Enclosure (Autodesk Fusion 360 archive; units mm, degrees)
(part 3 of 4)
sketch "Sketch47" plane through (0, 0, 11.21) normal (0, 0, 1) x axis (-1, 0, 0)
  line L1 (-247.2132, -356.5) -> (-247.2132, -307.5)
  line L2 (-303.7132, -364) -> (-254.7132, -364)
  line L3 (-311.2132, -307.5) -> (-311.2132, -356.5)
  line L4 (-254.7132, -300) -> (-303.7132, -300)
  line L5 (-147.4232, -321.735) -> (-217.4232, -321.735)
  line L6 (-217.4232, -336.735) -> (-147.4232, -336.735)
  line L7 (-110.1332, -364) -> (-61.1332, -364)
  line L8 (-117.6332, -307.5) -> (-117.6332, -356.5)
  line L9 (-61.1332, -300) -> (-110.1332, -300)
  line L10 (-53.6332, -356.5) -> (-53.6332, -307.5)
  line L11 (-33.6332, -368.47) -> (-331.2132, -368.47)
  line L12 (-33.6332, -290) -> (-33.6332, -368.47)
  line L13 (-331.2132, -290) -> (-33.6332, -290)
  line L14 (-331.2132, -368.47) -> (-331.2132, -290)
  line L15 (-333.79, -258.79) -> (-36.21, -258.79)
  line L16 (-348.79, -36.21) -> (-348.79, -243.79)
  line L17 (-36.21, -21.21) -> (-333.79, -21.21)
  line L18 (-21.21, -243.79) -> (-21.21, -36.21)
  line L19 (-25, -270) -> (-345, -270)
  line L20 (-10, -25) -> (-10, -255)
  line L21 (-345, -10) -> (-25, -10)
  line L22 (-360, -255) -> (-360, -25)
  line L23 (-175, -248.79) -> (-46.21, -248.79)
  line L24 (-325.1297, -248.79) -> (-195, -248.79)
  line L25 (-338.79, -44.8703) -> (-338.79, -235.1297)
  line L26 (-195, -31.21) -> (-325.1297, -31.21)
  line L27 (-44.8703, -31.21) -> (-175, -31.21)
  line L28 (-31.21, -233.79) -> (-31.21, -44.8703)
  line L29 (-36.21, -258.79) -> (-333.79, -258.79)
  line L30 (-21.21, -36.21) -> (-21.21, -243.79)
  line L31 (-333.79, -21.21) -> (-36.21, -21.21)
  line L32 (-348.79, -243.79) -> (-348.79, -36.21)
  line L33 (-58.6332, -356.5) -> (-58.6332, -307.5)
  line L34 (-110.1332, -359) -> (-61.1332, -359)
  line L35 (-112.6332, -307.5) -> (-112.6332, -356.5)
  line L36 (-61.1332, -305) -> (-110.1332, -305)
  line L37 (-117.6332, -356.5) -> (-117.6332, -307.5)
  line L38 (-61.1332, -364) -> (-110.1332, -364)
  line L39 (-53.6332, -307.5) -> (-53.6332, -356.5)
  line L40 (-110.1332, -300) -> (-61.1332, -300)
  line L41 (-254.7132, -305) -> (-303.7132, -305)
  line L42 (-252.2132, -356.5) -> (-252.2132, -307.5)
  line L43 (-303.7132, -359) -> (-254.7132, -359)
  line L44 (-306.2132, -307.5) -> (-306.2132, -356.5)
  line L45 (-254.7132, -305) -> (-303.7132, -305)
  line L46 (-254.7132, -364) -> (-303.7132, -364)
  line L47 (-247.2132, -307.5) -> (-247.2132, -356.5)
  line L48 (-303.7132, -300) -> (-254.7132, -300)
  line L49 (-311.2132, -356.5) -> (-311.2132, -307.5)
  arc A1 centre (-254.7132, -356.5) radius 7.5 clockwise from (-247.2132, -356.5) to (-254.7132, -364)
  arc A2 centre (-303.7132, -356.5) radius 7.5 clockwise from (-303.7132, -364) to (-311.2132, -356.5)
  arc A3 centre (-303.7132, -307.5) radius 7.5 clockwise from (-311.2132, -307.5) to (-303.7132, -300)
  arc A4 centre (-254.7132, -307.5) radius 7.5 clockwise from (-254.7132, -300) to (-247.2132, -307.5)
  arc A5 centre (-217.4232, -329.235) radius 7.5 clockwise from (-217.4232, -336.735) to (-217.4232, -321.735)
  arc A6 centre (-147.4232, -329.235) radius 7.5 clockwise from (-147.4232, -321.735) to (-147.4232, -336.735)
  arc A7 centre (-110.1332, -356.5) radius 7.5 clockwise from (-110.1332, -364) to (-117.6332, -356.5)
  arc A8 centre (-110.1332, -307.5) radius 7.5 clockwise from (-117.6332, -307.5) to (-110.1332, -300)
  arc A9 centre (-61.1332, -307.5) radius 7.5 clockwise from (-61.1332, -300) to (-53.6332, -307.5)
  arc A10 centre (-61.1332, -356.5) radius 7.5 clockwise from (-53.6332, -356.5) to (-61.1332, -364)
  arc A11 centre (-333.79, -243.79) radius 15 clockwise from (-333.79, -258.79) to (-348.79, -243.79)
  arc A12 centre (-333.79, -36.21) radius 15 clockwise from (-348.79, -36.21) to (-333.79, -21.21)
  arc A13 centre (-36.21, -36.21) radius 15 clockwise from (-36.21, -21.21) to (-21.21, -36.21)
  arc A14 centre (-36.21, -243.79) radius 15 clockwise from (-21.21, -243.79) to (-36.21, -258.79)
  arc A15 centre (-25, -255) radius 15 clockwise from (-10, -255) to (-25, -270)
  arc A16 centre (-25, -25) radius 15 clockwise from (-25, -10) to (-10, -25)
  arc A17 centre (-345, -25) radius 15 clockwise from (-360, -25) to (-345, -10)
  arc A18 centre (-345, -255) radius 15 clockwise from (-345, -270) to (-360, -255)
  arc A19 centre (-46.21, -233.79) radius 15 clockwise from (-44.9029, -248.7329) to (-46.21, -248.79)
  arc A20 centre (-185, -248.79) radius 10 clockwise from (-195, -248.79) to (-175, -248.79)
  arc A21 centre (-333.79, -243.79) radius 10 clockwise from (-338.79, -235.1297) to (-325.1297, -248.79)
  arc A22 centre (-333.79, -36.21) radius 10 clockwise from (-325.1297, -31.21) to (-338.79, -44.8703)
  arc A23 centre (-185, -31.21) radius 10 clockwise from (-175, -31.21) to (-195, -31.21)
  arc A24 centre (-36.21, -36.21) radius 10 clockwise from (-31.21, -44.8703) to (-44.8703, -31.21)
  arc A25 centre (-46.21, -233.79) radius 15 clockwise from (-31.21, -233.79) to (-31.2671, -235.0971)
  arc A26 centre (-36.21, -243.79) radius 10 clockwise from (-44.9029, -248.7329) to (-31.2671, -235.0971)
  arc A27 centre (-36.21, -243.79) radius 15 clockwise from (-21.21, -243.79) to (-36.21, -258.79)
  arc A28 centre (-36.21, -36.21) radius 15 clockwise from (-36.21, -21.21) to (-21.21, -36.21)
  arc A29 centre (-333.79, -36.21) radius 15 clockwise from (-348.79, -36.21) to (-333.79, -21.21)
  arc A30 centre (-333.79, -243.79) radius 15 clockwise from (-333.79, -258.79) to (-348.79, -243.79)
  arc A31 centre (-61.1332, -307.5) radius 2.5 clockwise from (-61.1332, -305) to (-58.6332, -307.5)
  arc A32 centre (-61.1332, -356.5) radius 2.5 clockwise from (-58.6332, -356.5) to (-61.1332, -359)
  arc A33 centre (-110.1332, -356.5) radius 2.5 clockwise from (-110.1332, -359) to (-112.6332, -356.5)
  arc A34 centre (-110.1332, -307.5) radius 2.5 clockwise from (-112.6332, -307.5) to (-110.1332, -305)
  arc A35 centre (-110.1332, -307.5) radius 7.5 clockwise from (-117.6332, -307.5) to (-110.1332, -300)
  arc A36 centre (-110.1332, -356.5) radius 7.5 clockwise from (-110.1332, -364) to (-117.6332, -356.5)
  arc A37 centre (-61.1332, -356.5) radius 7.5 clockwise from (-53.6332, -356.5) to (-61.1332, -364)
  arc A38 centre (-61.1332, -307.5) radius 7.5 clockwise from (-61.1332, -300) to (-53.6332, -307.5)
  arc A39 centre (-254.7132, -307.5) radius 2.5 clockwise from (-254.7132, -305) to (-252.2132, -307.5)
  arc A40 centre (-254.7132, -356.5) radius 2.5 clockwise from (-252.2132, -356.5) to (-254.7132, -359)
  arc A41 centre (-303.7132, -356.5) radius 2.5 clockwise from (-303.7132, -359) to (-306.2132, -356.5)
  arc A42 centre (-303.7132, -307.5) radius 2.5 clockwise from (-306.2132, -307.5) to (-303.7132, -305)
  arc A43 centre (-303.7132, -356.5) radius 7.5 clockwise from (-303.7132, -364) to (-311.2132, -356.5)
  arc A44 centre (-254.7132, -356.5) radius 7.5 clockwise from (-247.2132, -356.5) to (-254.7132, -364)
  arc A45 centre (-254.7132, -307.5) radius 7.5 clockwise from (-254.7132, -300) to (-247.2132, -307.5)
  arc A46 centre (-303.7132, -307.5) radius 7.5 clockwise from (-311.2132, -307.5) to (-303.7132, -300)
sketch "Sketch48" plane through (0, -162.2304, 59.047) normal (0, 0.9397, -0.342) x axis (-1, 0, 0)
  line L1 (-46.5, 2.5998) -> (-46.5, -10.4002)
  line L2 (-45, 2.5998) -> (-46.5, 2.5998)
  line L3 (-41.5, 7.5998) -> (-41.5, 6.0998)
  line L4 (41.5, 7.5998) -> (-41.5, 7.5998)
  line L5 (41.5, 6.0998) -> (41.5, 7.5998)
  line L6 (46.5, 2.5998) -> (45, 2.5998)
  line L7 (46.5, -10.4002) -> (46.5, 2.5998)
  line L8 (45, -10.4002) -> (46.5, -10.4002)
  line L9 (41.5, -15.4002) -> (41.5, -13.9002)
  line L10 (-41.5, -15.4002) -> (41.5, -15.4002)
  line L11 (-41.5, -13.9002) -> (-41.5, -15.4002)
  line L12 (-46.5, -10.4002) -> (-45, -10.4002)
  line L13 (-47, -15.9002) -> (-47, 8.0998)
  line L14 (47, -15.9002) -> (-47, -15.9002)
  line L15 (47, 8.0998) -> (47, -15.9002)
  line L16 (-47, 8.0998) -> (47, 8.0998)
  arc A1 centre (-45, 6.0998) radius 3.5 clockwise from (-41.5, 6.0998) to (-45, 2.5998)
  arc A2 centre (45, 6.0998) radius 3.5 clockwise from (45, 2.5998) to (41.5, 6.0998)
  arc A3 centre (45, -13.9002) radius 3.5 clockwise from (41.5, -13.9002) to (45, -10.4002)
  arc A4 centre (-45, -13.9002) radius 3.5 clockwise from (-45, -10.4002) to (-41.5, -13.9002)
  circle C1 centre (45, -13.9002) radius 1.5
  circle C2 centre (-45, 6.0998) radius 1.5
  circle C3 centre (45, 6.0998) radius 1.5
  circle C4 centre (-45, -13.9002) radius 1.5
offset_faces "OffsetFaces4" distance -1
fillet "Fillet7" radius 3.5
split "Split3" bodies "CASE (1)"
offset_faces "OffsetFaces6" distance 6
offset_faces "OffsetFaces7" distance 6
offset_faces "OffsetFaces8" distance -6
offset_faces "OffsetFaces9" distance -6
sketch "Sketch63" plane through (0, -160.351, 58.363) normal (0, -0.9397, 0.342) x axis (1, 0, 0)
  line L1 (50, 12.0998) -> (50, -19.9002)
  line L2 (-45, 17.0998) -> (45, 17.0998)
  line L3 (-50, -19.9002) -> (-50, 12.0998)
  line L4 (45, -24.9002) -> (-45, -24.9002)
  line L5 (-41.5, -13.9002) -> (-41.5, -15.4002)
  line L6 (-46.5, -10.4002) -> (-45, -10.4002)
  line L7 (-46.5, 2.5998) -> (-46.5, -10.4002)
  line L8 (-45, 2.5998) -> (-46.5, 2.5998)
  line L9 (-41.5, 7.5998) -> (-41.5, 6.0998)
  line L10 (41.5, 7.5998) -> (-41.5, 7.5998)
  line L11 (41.5, 6.0998) -> (41.5, 7.5998)
  line L12 (46.5, 2.5998) -> (45, 2.5998)
  line L13 (46.5, -10.4002) -> (46.5, 2.5998)
  line L14 (45, -10.4002) -> (46.5, -10.4002)
  line L15 (41.5, -15.4002) -> (41.5, -13.9002)
  line L16 (-41.5, -15.4002) -> (41.5, -15.4002)
  line L17 (44.5, -16.9002) -> (-44.5, -16.9002)
  line L18 (48, 5.5998) -> (48, -13.4002)
  line L19 (-44.5, 9.0998) -> (44.5, 9.0998)
  line L20 (-48, -13.4002) -> (-48, 5.5998)
  arc A1 centre (45, -19.9002) radius 5 clockwise from (50, -19.9002) to (45, -24.9002)
  arc A2 centre (45, 12.0998) radius 5 clockwise from (45, 17.0998) to (50, 12.0998)
  arc A3 centre (-45, 12.0998) radius 5 clockwise from (-50, 12.0998) to (-45, 17.0998)
  arc A4 centre (-45, -19.9002) radius 5 clockwise from (-45, -24.9002) to (-50, -19.9002)
  circle C1 centre (45, 6.0998) radius 1.5
  circle C2 centre (-45, -13.9002) radius 1.5
  circle C3 centre (45, -13.9002) radius 1.5
  circle C4 centre (-45, 6.0998) radius 1.5
  arc A5 centre (-45, -13.9002) radius 3.5 clockwise from (-45, -10.4002) to (-41.5, -13.9002)
  arc A6 centre (-45, 6.0998) radius 3.5 clockwise from (-41.5, 6.0998) to (-45, 2.5998)
  arc A7 centre (45, 6.0998) radius 3.5 clockwise from (45, 2.5998) to (41.5, 6.0998)
  arc A8 centre (45, -13.9002) radius 3.5 clockwise from (41.5, -13.9002) to (45, -10.4002)
  arc A9 centre (44.5, -13.4002) radius 3.5 clockwise from (48, -13.4002) to (44.5, -16.9002)
  arc A10 centre (44.5, 5.5998) radius 3.5 clockwise from (44.5, 9.0998) to (48, 5.5998)
  arc A11 centre (-44.5, 5.5998) radius 3.5 clockwise from (-48, 5.5998) to (-44.5, 9.0998)
  arc A12 centre (-44.5, -13.4002) radius 3.5 clockwise from (-44.5, -16.9002) to (-48, -13.4002)
extrude "Extrude44" cut sketch "Sketch63" profile of C1 C2 C3 C4 L5 A5 L6 L7 L8 A6 L9 L10 L11 A7 L12 L13 L14 A8 L15 L16 A9 L17 L18 A10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 against normal blind 2.2 (magnitude of "-2 mm - prt_tol")
combine "Combine2" bodies "CASE (1)"
extrude "Extrude45" add of existing geometry blind 8
extrude "Extrude46" cut of existing geometry blind -2
extrude "Extrude47" add of existing geometry blind 2
sketch "Sketch64" plane through (0, -118.79, 0) normal (0, 1, 0) x axis (-1, 0, 0)
  line L1 (35, 42.945) -> (-35, 42.945)
  line L2 (-35, 57.945) -> (35, 57.945)
  line L3 (35, 52.945) -> (-35, 52.945)
  line L4 (-35, 47.945) -> (35, 47.945)
  line L5 (-37.5, 50.445) -> (-42.5, 50.445)
  line L6 (42.5, 50.445) -> (37.5, 50.445)
  arc A1 centre (35, 50.445) radius 7.5 clockwise from (35, 57.945) to (35, 42.945)
  arc A2 centre (-35, 50.445) radius 7.5 clockwise from (-35, 42.945) to (-35, 57.945)
  arc A3 centre (-35, 50.445) radius 2.5 clockwise from (-35, 47.945) to (-35, 52.945)
  arc A4 centre (35, 50.445) radius 2.5 clockwise from (35, 52.945) to (35, 47.945)
  circle C1 centre (-40, 50.445) radius 1.25
  circle C2 centre (40, 50.445) radius 1.25
  point P12 (-42.5, 50.445)
  point P13 (-37.5, 50.445)
  point P14 (37.5, 50.445)
  point P15 (42.5, 50.445)
  point P16 (-40, 50.445)
  point P17 (40, 50.445)
  midpoint A2 P12
  midpoint A3 P13
  midpoint A4 P14
  midpoint A1 P15
  midpoint L5 P16
  midpoint L6 P17
  dimension "d464" diameter C1 = 2.5
  dimension "d465" diameter C2 = 2.5
extrude "Extrude48" cut sketch "Sketch64" profile of C1 C2 distance 5
sketch "Sketch65" plane through (0, -113.79, 0) normal (0, 1, 0) x axis (-1, 0, 0)
  line L1 (35, 37.945) -> (-35, 37.945)
  line L2 (-35, 62.945) -> (35, 62.945)
  line L3 (-35, 47.945) -> (35, 47.945)
  line L4 (35, 52.945) -> (-35, 52.945)
  circle C1 centre (-40, 50.445) radius 1.25
  circle C2 centre (40, 50.445) radius 1.25
  circle C3 centre (-44.8333, 50.445) radius 1.5
  circle C4 centre (44.8333, 50.445) radius 1.5
  arc A1 centre (-35, 50.445) radius 12.5 clockwise from (-35, 37.945) to (-35, 62.945)
  arc A2 centre (35, 50.445) radius 12.5 clockwise from (35, 62.945) to (35, 37.945)
  arc A3 centre (-35, 50.445) radius 2.5 clockwise from (-35, 47.945) to (-35, 52.945)
  arc A4 centre (35, 50.445) radius 2.5 clockwise from (35, 52.945) to (35, 47.945)
  circle C5 centre (-40, 50.445) radius 2
  circle C6 centre (40, 50.445) radius 2
  concentric C1 C5
  concentric C2 C6
  dimension "d468" diameter C5 = 4
  dimension "d469" diameter C6 = 4
extrude "Extrude49" cut sketch "Sketch65" profile of C1 C2 C5 C6 against normal blind 2
sketch "Sketch66" plane through (0, -113.79, 0) normal (0, 1, 0) x axis (-1, 0, 0)
  line L1 (-35, 47.945) -> (35, 47.945)
  line L2 (35, 52.945) -> (-35, 52.945)
  line L3 (35, 37.945) -> (-35, 37.945)
  line L4 (-35, 62.945) -> (35, 62.945)
  line L5 (47.5, 50.445) -> (-47.5, 50.445)
  line L6 (35, 52.945) -> (-35, 52.945)
  line L7 (-35, 47.945) -> (35, 47.945)
  arc A1 centre (-35, 50.445) radius 2.5 clockwise from (-35, 47.945) to (-35, 52.945)
  arc A2 centre (35, 50.445) radius 2.5 clockwise from (35, 52.945) to (35, 47.945)
  arc A3 centre (-35, 50.445) radius 12.5 clockwise from (-35, 37.945) to (-35, 62.945)
  arc A4 centre (35, 50.445) radius 12.5 clockwise from (35, 62.945) to (35, 37.945)
  circle C1 centre (44.8333, 50.445) radius 1.5
  circle C2 centre (-44.8333, 50.445) radius 1.5
  circle C3 centre (40, 50.445) radius 2
  circle C4 centre (-40, 50.445) radius 2
  arc A5 centre (-35, 50.445) radius 2.5 clockwise from (-35, 47.945) to (-35, 52.945)
  arc A6 centre (35, 50.445) radius 2.5 clockwise from (35, 52.945) to (35, 47.945)
  circle C5 centre (-35, 50.445) radius 2.4674
  circle C6 centre (-32.5326, 50.445) radius 2.5
  circle C7 centre (35, 50.445) radius 2.5
  circle C8 centre (32.5, 50.445) radius 2.5
  point P16 (-47.5, 50.445)
  point P17 (47.5, 50.445)
  point P25 (-32.5326, 50.445)
  point P27 (32.5, 50.445)
  midpoint A3 P16
  midpoint A4 P17
  concentric A5 C5
  coincident C5 P25
  coincident L5 P25
  concentric A6 C7
  coincident C7 P27
  coincident L5 P27
  tangent L2 C6
  tangent L2 C8
extrude "Extrude50" add sketch "Sketch66" profile of L1 A1 L2 A2 C6 C8 against normal blind 5
extrude "Extrude51" cut of existing geometry blind -2
sketch "Sketch49" plane through (0, -162.2304, 59.047) normal (0, 0.9397, -0.342) x axis (-1, 0, 0)
  line L1 (-46.5, 2.5998) -> (-46.5, -10.4002)
  line L2 (-45, 2.5998) -> (-46.5, 2.5998)
  line L3 (-41.5, 7.5998) -> (-41.5, 6.0998)
  line L4 (41.5, 7.5998) -> (-41.5, 7.5998)
  line L5 (41.5, 6.0998) -> (41.5, 7.5998)
  line L6 (46.5, 2.5998) -> (45, 2.5998)
  line L7 (46.5, -10.4002) -> (46.5, 2.5998)
  line L8 (45, -10.4002) -> (46.5, -10.4002)
  line L9 (41.5, -15.4002) -> (41.5, -13.9002)
  line L10 (-41.5, -15.4002) -> (41.5, -15.4002)
  line L11 (-41.5, -13.9002) -> (-41.5, -15.4002)
  line L12 (-46.5, -10.4002) -> (-45, -10.4002)
  line L13 (-44.5, 9.0998) -> (44.5, 9.0998)
  line L14 (-48, -13.4002) -> (-48, 5.5998)
  line L15 (44.5, -16.9002) -> (-44.5, -16.9002)
  line L16 (48, 5.5998) -> (48, -13.4002)
  line L17 (28, -10.1502) -> (4, 3.8498)
  line L18 (4, -10.1502) -> (28, 3.8498)
  line L19 (-16, -3.9002) -> (-46.5, -3.9002)
  line L20 (-31.25, -15) -> (-31.25, 6.0998)
  circle C1 centre (-45, -13.9002) radius 1.5
  circle C2 centre (45, 6.0998) radius 1.5
  circle C3 centre (-45, 6.0998) radius 1.5
  circle C4 centre (45, -13.9002) radius 1.5
  arc A1 centre (-45, 6.0998) radius 3.5 clockwise from (-41.5, 6.0998) to (-45, 2.5998)
  arc A2 centre (45, 6.0998) radius 3.5 clockwise from (45, 2.5998) to (41.5, 6.0998)
  arc A3 centre (45, -13.9002) radius 3.5 clockwise from (41.5, -13.9002) to (45, -10.4002)
  arc A4 centre (-45, -13.9002) radius 3.5 clockwise from (-45, -10.4002) to (-41.5, -13.9002)
  arc A5 centre (44.5, 5.5998) radius 3.5 clockwise from (44.5, 9.0998) to (48, 5.5998)
  arc A6 centre (-44.5, 5.5998) radius 3.5 clockwise from (-48, 5.5998) to (-44.5, 9.0998)
  arc A7 centre (-44.5, -13.4002) radius 3.5 clockwise from (-44.5, -16.9002) to (-48, -13.4002)
  arc A8 centre (44.5, -13.4002) radius 3.5 clockwise from (48, -13.4002) to (44.5, -16.9002)
component_insert "Component Insert"
sketch "Sketch50" plane through (677.5932, -130, -582.7678) normal (0, -1, 0) x axis (1, 0, 0)
  line L1 (-742.3832, 605.9478) -> (-742.3832, 654.9478)
  line L2 (-798.8832, 598.4478) -> (-749.8832, 598.4478)
  line L3 (-806.3832, 654.9478) -> (-806.3832, 605.9478)
  line L4 (-749.8832, 662.4478) -> (-798.8832, 662.4478)
  line L5 (-642.5932, 640.7128) -> (-712.5932, 640.7128)
  line L6 (-712.5932, 625.7128) -> (-642.5932, 625.7128)
  line L7 (-605.3032, 598.4478) -> (-556.3032, 598.4478)
  line L8 (-612.8032, 654.9478) -> (-612.8032, 605.9478)
  line L9 (-556.3032, 662.4478) -> (-605.3032, 662.4478)
  line L10 (-548.8032, 605.9478) -> (-548.8032, 654.9478)
  line L11 (-528.8032, 593.9778) -> (-826.3832, 593.9778)
  line L12 (-528.8032, 672.4478) -> (-528.8032, 593.9778)
  line L13 (-826.3832, 672.4478) -> (-528.8032, 672.4478)
  line L14 (-826.3832, 593.9778) -> (-826.3832, 672.4478)
  arc A1 centre (-749.8832, 605.9478) radius 7.5 clockwise from (-742.3832, 605.9478) to (-749.8832, 598.4478)
  arc A2 centre (-798.8832, 605.9478) radius 7.5 clockwise from (-798.8832, 598.4478) to (-806.3832, 605.9478)
  arc A3 centre (-798.8832, 654.9478) radius 7.5 clockwise from (-806.3832, 654.9478) to (-798.8832, 662.4478)
  arc A4 centre (-749.8832, 654.9478) radius 7.5 clockwise from (-749.8832, 662.4478) to (-742.3832, 654.9478)
  arc A5 centre (-712.5932, 633.2128) radius 7.5 clockwise from (-712.5932, 625.7128) to (-712.5932, 640.7128)
  arc A6 centre (-642.5932, 633.2128) radius 7.5 clockwise from (-642.5932, 640.7128) to (-642.5932, 625.7128)
  arc A7 centre (-605.3032, 605.9478) radius 7.5 clockwise from (-605.3032, 598.4478) to (-612.8032, 605.9478)
  arc A8 centre (-605.3032, 654.9478) radius 7.5 clockwise from (-612.8032, 654.9478) to (-605.3032, 662.4478)
  arc A9 centre (-556.3032, 654.9478) radius 7.5 clockwise from (-556.3032, 662.4478) to (-548.8032, 654.9478)
  arc A10 centre (-556.3032, 605.9478) radius 7.5 clockwise from (-548.8032, 605.9478) to (-556.3032, 598.4478)
sketch "Sketch51" plane through (677.5932, -130, -582.7678) normal (0, -1, 0) x axis (1, 0, 0)
  line L1 (-548.8032, 605.9478) -> (-548.8032, 654.9478)
  line L2 (-605.3032, 598.4478) -> (-556.3032, 598.4478)
  line L3 (-556.3032, 662.4478) -> (-605.3032, 662.4478)
  line L4 (-612.8032, 654.9478) -> (-612.8032, 605.9478)
  line L5 (-612.8032, 662.4478) -> (-548.8032, 662.4478)
  line L6 (-612.8032, 598.4478) -> (-612.8032, 662.4478)
  line L7 (-548.8032, 598.4478) -> (-612.8032, 598.4478)
  line L8 (-548.8032, 662.4478) -> (-548.8032, 598.4478)
  line L9 (-612.8032, 630.4478) -> (-548.8032, 630.4478)
  line L10 (-580.8032, 662.4478) -> (-580.8032, 598.4478)
  arc A1 centre (-556.3032, 605.9478) radius 7.5 clockwise from (-548.8032, 605.9478) to (-556.3032, 598.4478)
  arc A2 centre (-556.3032, 654.9478) radius 7.5 clockwise from (-556.3032, 662.4478) to (-548.8032, 654.9478)
  arc A3 centre (-605.3032, 654.9478) radius 7.5 clockwise from (-612.8032, 654.9478) to (-605.3032, 662.4478)
  arc A4 centre (-605.3032, 605.9478) radius 7.5 clockwise from (-605.3032, 598.4478) to (-612.8032, 605.9478)
  circle C1 centre (-557.8032, 630.4478) radius 1.5
  circle C2 centre (-580.8032, 601.6976) radius 1.375
  circle C3 centre (-580.8032, 613.1976) radius 1.625
  circle C4 centre (-569.3032, 630.4478) radius 1.75
  circle C5 centre (-580.8032, 624.6976) radius 1.875
  circle C6 centre (-580.8032, 630.4476) radius 2
  circle C7 centre (-580.8032, 630.4476) radius 5.75
  circle C8 centre (-580.8032, 630.4476) radius 11.5
  circle C9 centre (-580.8032, 630.4476) radius 17.25
  circle C10 centre (-580.8032, 630.4476) radius 23
  circle C11 centre (-580.8032, 630.4476) radius 28.75
  circle C12 centre (-575.3346, 628.6708) radius 1.875
  circle C13 centre (-577.4234, 635.0995) radius 1.875
  circle C14 centre (-584.1829, 635.0995) radius 1.875
  circle C15 centre (-586.2717, 628.6708) radius 1.875
  circle C16 centre (-571.9937, 637.8398) radius 1.75
  circle C17 centre (-578.8063, 641.7729) radius 1.75
  circle C18 centre (-586.5533, 640.4068) radius 1.75
  circle C19 centre (-591.6097, 634.3807) radius 1.75
  circle C20 centre (-591.6096, 626.5143) radius 1.75
  circle C21 centre (-586.553, 620.4883) radius 1.75
  circle C22 centre (-578.8061, 619.1224) radius 1.75
  circle C23 centre (-571.9936, 623.0557) radius 1.75
  circle C24 centre (-572.7867, 615.1735) radius 1.625
  circle C25 centre (-566.6067, 620.6485) radius 1.625
  circle C26 centre (-563.6789, 628.3684) radius 1.625
  circle C27 centre (-564.6741, 636.5646) radius 1.625
  circle C28 centre (-569.3643, 643.3594) radius 1.625
  circle C29 centre (-576.675, 647.1964) radius 1.625
  circle C30 centre (-584.9314, 647.1964) radius 1.625
  circle C31 centre (-592.242, 643.3594) radius 1.625
  circle C32 centre (-596.9322, 636.5646) radius 1.625
  circle C33 centre (-597.9274, 628.3684) radius 1.625
  circle C34 centre (-594.9996, 620.6485) radius 1.625
  circle C35 centre (-588.8196, 615.1735) radius 1.625
  circle C36 centre (-559.1903, 638.3142) radius 1.5
  circle C37 centre (-563.1842, 645.2318) radius 1.5
  circle C38 centre (-569.3033, 650.3663) radius 1.5
  circle C39 centre (-576.8094, 653.0982) radius 1.5
  circle C40 centre (-584.7972, 653.0982) radius 1.5
  circle C41 centre (-592.3033, 650.3661) radius 1.5
  circle C42 centre (-598.4223, 645.2316) radius 1.5
  circle C43 centre (-602.4161, 638.314) radius 1.5
  circle C44 centre (-603.8032, 630.4475) radius 1.5
  circle C45 centre (-602.416, 622.581) radius 1.5
  circle C46 centre (-598.4221, 615.6634) radius 1.5
  circle C47 centre (-592.303, 610.529) radius 1.5
  circle C48 centre (-584.7969, 607.797) radius 1.5
  circle C49 centre (-576.8091, 607.7971) radius 1.5
  circle C50 centre (-569.303, 610.5291) radius 1.5
  circle C51 centre (-563.184, 615.6636) radius 1.5
  circle C52 centre (-572.3289, 602.9749) radius 1.375
  circle C53 centre (-564.6077, 606.6933) radius 1.375
  circle C54 centre (-558.3255, 612.5223) radius 1.375
  circle C55 centre (-554.0405, 619.9441) radius 1.375
  circle C56 centre (-552.1335, 628.2991) radius 1.375
  circle C57 centre (-552.774, 636.8451) radius 1.375
  circle C58 centre (-555.9049, 644.8226) radius 1.375
  circle C59 centre (-561.2482, 651.5229) radius 1.375
  circle C60 centre (-568.329, 656.3505) radius 1.375
  circle C61 centre (-576.5182, 658.8765) radius 1.375
  circle C62 centre (-585.0881, 658.8765) radius 1.375
  circle C63 centre (-593.2773, 656.3505) radius 1.375
  circle C64 centre (-600.3581, 651.5229) radius 1.375
  circle C65 centre (-605.7014, 644.8226) radius 1.375
  circle C66 centre (-608.8323, 636.8451) radius 1.375
  circle C67 centre (-609.4728, 628.2991) radius 1.375
  circle C68 centre (-607.5658, 619.9441) radius 1.375
  circle C69 centre (-603.2808, 612.5223) radius 1.375
  circle C70 centre (-596.9986, 606.6933) radius 1.375
  circle C71 centre (-589.2774, 602.9749) radius 1.375
  circle C72 centre (-559.1902, 622.5813) radius 1.5
  point P22 (-580.8032, 624.6976)
  point P21 (-569.3032, 630.4478)
  point P20 (-580.8032, 613.1976)
  point P18 (-557.8032, 630.4478)
  point P19 (-580.8032, 601.6976)
  point P29 (-548.8032, 630.4478)
  point P30 (-612.8032, 630.4478)
  point P91 (-580.8032, 598.4478)
  point P92 (-580.8032, 662.4478)
  horizontal L5
  vertical L6
  horizontal L7
  vertical L8
  collinear L3 L5
  collinear L1 L8
  collinear L2 L7
  collinear L4 L6
  concentric C6 C7
  coincident P22 C7
  concentric C7 C8
  coincident P21 C8
  concentric C7 C9
  coincident P20 C9
  concentric C8 C10
  coincident P18 C10
  concentric C7 C11
  coincident P19 C11
  midpoint L1 P29
  midpoint L6 P30
  midpoint L2 P91
  midpoint L3 P92
  coincident P22 L10
  coincident P21 L9
  coincident P20 L10
  coincident P18 L9
  coincident P19 L10
  dimension "d285" diameter C1 = 3
  dimension "d287" diameter C2 = 2.75
  dimension "d289" diameter C3 = 3.25
  dimension "d290" diameter C4 = 3.5
  dimension "d291" diameter C5 = 3.75
  dimension "d292" diameter C6 = 4
  dimension "d297" diameter C7 = 11.5
  dimension "d298" diameter C8 = 23
  dimension "d299" diameter C9 = 34.5
  dimension "d300" diameter C10 = 46
  dimension "d301" diameter C11 = 57.5
  dimension "d303" C-Pattern1-Angle = 360
  dimension "d305" C-Pattern2-Angle = 360
  dimension "d307" C-Pattern3-Angle = 360
  dimension "d309" C-Pattern4-Angle = 360
  dimension "d311" C-Pattern5-Angle = 360
extrude "Extrude38" new body sketch "Sketch51" profile of L1 L2 A1 A2 L3 A3 L4 A4 L5 L6 L7 L8 C1 C2 C3 C4 C5 C6 C12 C13 C14 C15 C16 C17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 no distance stored bodies "SPEAKER_1"
component_from_bodies "Body->Comp22"
canvas "Canvas3"
sketch "Sketch52" plane through (0, 0, 100.89) normal (0, 0, 1) x axis (-1, 0, 0)
  line L1 (-70.4881, 25.0153) -> (-77.9184, 36.8936)
  line L2 (-57.3532, 20.7882) -> (-62.858, 20.7882)
  line L3 (-44.6522, 33.8527) -> (-50.4482, 24.6087)
  line L4 (-0.9873, 49.5999) -> (-39.979, 37.4526)
  line L5 (33.6145, -91.6878) -> (56.037, -74.7812)
  curve K1 (-2.6931, -89.0142) -> (33.6145, -91.6878)
  line L6 (-103.79, -106.0016) -> (-39.0028, -106.0016)
  line L7 (-115.79, 34.151) -> (-115.79, -94.0016)
  line L8 (-84.7008, 40.651) -> (-109.29, 40.651)
  line L9 (-148.79, 118.79) -> (148.79, 118.79)
  line L10 (-163.79, -103.79) -> (-163.79, 103.79)
  line L11 (148.79, -118.79) -> (-148.79, -118.79)
  line L12 (163.79, 103.79) -> (163.79, -103.79)
  arc A1 centre (-84.7008, 32.651) radius 8 clockwise from (-84.7008, 40.651) to (-77.9184, 36.8936)
  arc A2 centre (-62.858, 29.7882) radius 9 clockwise from (-62.858, 20.7882) to (-70.4881, 25.0153)
  arc A3 centre (-57.3532, 28.9382) radius 8.15 clockwise from (-50.4482, 24.6087) to (-57.3532, 20.7882)
  arc A4 centre (-37.4507, 29.3373) radius 8.5 clockwise from (-44.6522, 33.8527) to (-39.979, 37.4526)
  arc A5 centre (58.7121, 1.7076) radius 76.5356 clockwise from (-0.9873, 49.5999) to (56.037, -74.7812)
  arc A6 centre (-12.4884, -96.8605) radius 12.5504 clockwise from (-12.4884, -96.8605) to (-24.7901, -94.3742)
  arc A7 centre (-39.0028, -91.5016) radius 14.5 clockwise from (-24.7901, -94.3742) to (-39.0028, -106.0016)
  arc A8 centre (-103.79, -94.0016) radius 12 clockwise from (-103.79, -106.0016) to (-115.79, -94.0016)
  arc A9 centre (-109.29, 34.151) radius 6.5 clockwise from (-115.79, 34.151) to (-109.29, 40.651)
  arc A10 centre (148.79, 103.79) radius 15 clockwise from (148.79, 118.79) to (163.79, 103.79)
  arc A11 centre (-148.79, 103.79) radius 15 clockwise from (-163.79, 103.79) to (-148.79, 118.79)
  arc A12 centre (-148.79, -103.79) radius 15 clockwise from (-148.79, -118.79) to (-163.79, -103.79)
  arc A13 centre (148.79, -103.79) radius 15 clockwise from (163.79, -103.79) to (148.79, -118.79)
  circle C1 centre (135, 38) radius 3
  circle C2 centre (-60, 32) radius 3
  circle C3 centre (-12.4884, -95.702) radius 3
  circle C4 centre (132.3797, 40.2075) radius 4
  dimension "d314" diameter C1 = 6
  dimension "d315" diameter C2 = 6
  dimension "d316" diameter C3 = 6
  dimension "d370" diameter C4 = 8
extrude "Extrude1" cut sketch "Sketch52" profile of C1 C2 C3 C4 against normal blind 2
step "Arrange6" AngleFromX 0 Priority 500 AngleFromX 0 Priority 500 AngleFromX 0 Priority 500 originOffsetX 0 originOffsetY 0 envelopeLength 300 envelopeWidth 500 envelopeSpacing 0 grainDirection 0 objectSpacing 40 frameWidth 10 placementClearance 0
step "Arrange7" AngleFromX 0 Priority 500 AngleFromX 0 Priority 500 AngleFromX 0 Priority 500 originOffsetX 0 originOffsetY 0 envelopeLength 300 envelopeWidth 500 envelopeSpacing 0 grainDirection 0 objectSpacing 40 frameWidth 10 placementClearance 0
sketch "Sketch53" plane through (0, 0, 2) normal (0, 0, 1) x axis (-1, 0, 0)
  line L1 (-103.7748, -103.3019) -> (-91.8964, -95.8716)
  line L2 (-108.0018, -116.4368) -> (-108.0018, -110.932)
  line L3 (-94.9373, -129.1377) -> (-104.1813, -123.3418)
  line L4 (-79.1901, -172.8027) -> (-91.3374, -133.811)
  line L5 (-220.4778, -207.4045) -> (-203.5713, -229.827)
  curve K1 (-217.8042, -171.0969) -> (-220.4778, -207.4045)
  line L6 (-234.7917, -70) -> (-234.7917, -134.7872)
  line L7 (-94.639, -58) -> (-222.7917, -58)
  line L8 (-88.139, -89.0892) -> (-88.139, -64.5)
  line L9 (-10, -25) -> (-10, -322.58)
  line L10 (-232.58, -10) -> (-25, -10)
  line L11 (-247.58, -322.58) -> (-247.58, -25)
  line L12 (-25, -337.58) -> (-232.58, -337.58)
  circle C1 centre (-224.492, -161.3015) radius 3
  circle C2 centre (-96.79, -113.79) radius 3
  arc A1 centre (-96.139, -89.0892) radius 8 clockwise from (-88.139, -89.0892) to (-91.8964, -95.8716)
  arc A2 centre (-99.0018, -110.932) radius 9 clockwise from (-108.0018, -110.932) to (-103.7748, -103.3019)
  arc A3 centre (-99.8518, -116.4368) radius 8.15 clockwise from (-104.1813, -123.3418) to (-108.0018, -116.4368)
  arc A4 centre (-99.4527, -136.3392) radius 8.5 clockwise from (-94.9373, -129.1377) to (-91.3374, -133.811)
  arc A5 centre (-127.0824, -232.5021) radius 76.5356 clockwise from (-79.1901, -172.8027) to (-203.5713, -229.827)
  arc A6 centre (-225.6505, -161.3015) radius 12.5504 clockwise from (-223.1642, -148.9998) to (-217.8042, -171.0969)
  arc A7 centre (-220.2917, -134.7872) radius 14.5 clockwise from (-223.1642, -148.9998) to (-234.7917, -134.7872)
  arc A8 centre (-222.7917, -70) radius 12 clockwise from (-234.7917, -70) to (-222.7917, -58)
  arc A9 centre (-94.639, -64.5) radius 6.5 clockwise from (-94.639, -58) to (-88.139, -64.5)
  arc A10 centre (-25, -322.58) radius 15 clockwise from (-10, -322.58) to (-25, -337.58)
  arc A11 centre (-25, -25) radius 15 clockwise from (-25, -10) to (-10, -25)
  arc A12 centre (-232.58, -25) radius 15 clockwise from (-247.58, -25) to (-232.58, -10)
  arc A13 centre (-232.58, -322.58) radius 15 clockwise from (-232.58, -337.58) to (-247.58, -322.58)
  circle C3 centre (-88.5825, -306.1697) radius 4
step "Arrange8" AngleFromX 0 Priority 500 AngleFromX 0 Priority 500 AngleFromX 0 Priority 500 originOffsetX 0 originOffsetY 0 envelopeLength 270 envelopeWidth 400 envelopeSpacing 0 grainDirection 0 objectSpacing 20 frameWidth 10 placementClearance 0
sketch "Sketch54" plane through (0, 0, 0) normal (0, 0, 1) x axis (1, 0, 0)
  line L1 (103.7748, 103.3019) -> (91.8964, 95.8716)
  line L2 (108.0018, 116.4368) -> (108.0018, 110.932)
  line L3 (94.9373, 129.1377) -> (104.1813, 123.3418)
  line L4 (79.1901, 172.8027) -> (91.3374, 133.811)
  line L5 (220.4778, 207.4045) -> (203.5713, 229.827)
  curve K1 (217.8042, 171.0969) -> (220.4778, 207.4045)
  line L6 (234.7917, 70) -> (234.7917, 134.7872)
  line L7 (94.639, 58) -> (222.7917, 58)
  line L8 (88.139, 89.0892) -> (88.139, 64.5)
  line L9 (10, 25) -> (10, 322.58)
  line L10 (232.58, 10) -> (25, 10)
  line L11 (247.58, 322.58) -> (247.58, 25)
  line L12 (25, 337.58) -> (232.58, 337.58)
  line L13 (135.5019, 143.6581) -> (184.5019, 143.6581)
  line L14 (128.0019, 87.1581) -> (128.0019, 136.1581)
  line L15 (184.5019, 79.6581) -> (135.5019, 79.6581)
  line L16 (192.0019, 136.1581) -> (192.0019, 87.1581)
  line L17 (165.642, 268.6862) -> (165.642, 219.6862)
  line L18 (109.142, 276.1862) -> (158.142, 276.1862)
  line L19 (101.642, 219.6862) -> (101.642, 268.6862)
  line L20 (158.142, 212.1862) -> (109.142, 212.1862)
  circle C1 centre (224.492, 161.3015) radius 3
  circle C2 centre (96.79, 113.79) radius 3
  arc A1 centre (96.139, 89.0892) radius 8 clockwise from (88.139, 89.0892) to (91.8964, 95.8716)
  arc A2 centre (99.0018, 110.932) radius 9 clockwise from (108.0018, 110.932) to (103.7748, 103.3019)
  arc A3 centre (99.8518, 116.4368) radius 8.15 clockwise from (104.1813, 123.3418) to (108.0018, 116.4368)
  arc A4 centre (99.4527, 136.3392) radius 8.5 clockwise from (94.9373, 129.1377) to (91.3374, 133.811)
  arc A5 centre (127.0824, 232.5021) radius 76.5356 clockwise from (79.1901, 172.8027) to (203.5713, 229.827)
  arc A6 centre (225.6505, 161.3015) radius 12.5504 clockwise from (223.1642, 148.9998) to (217.8042, 171.0969)
  arc A7 centre (220.2917, 134.7872) radius 14.5 clockwise from (223.1642, 148.9998) to (234.7917, 134.7872)
  arc A8 centre (222.7917, 70) radius 12 clockwise from (234.7917, 70) to (222.7917, 58)
  arc A9 centre (94.639, 64.5) radius 6.5 clockwise from (94.639, 58) to (88.139, 64.5)
  arc A10 centre (25, 322.58) radius 15 clockwise from (10, 322.58) to (25, 337.58)
  arc A11 centre (25, 25) radius 15 clockwise from (25, 10) to (10, 25)
  arc A12 centre (232.58, 25) radius 15 clockwise from (247.58, 25) to (232.58, 10)
  arc A13 centre (232.58, 322.58) radius 15 clockwise from (232.58, 337.58) to (247.58, 322.58)
  circle C3 centre (165.752, 111.6581) radius 1.875
  circle C4 centre (175.2761, 119.6746) radius 1.625
  circle C5 centre (161.7789, 117.1267) radius 1.875
  circle C6 centre (183.7564, 127.8536) radius 1.375
  circle C7 centre (155.3502, 115.0379) radius 1.875
  circle C8 centre (177.9274, 89.1805) radius 1.375
  circle C9 centre (169.8011, 125.8546) radius 1.625
  circle C10 centre (187.4748, 120.1323) radius 1.375
  circle C11 centre (145.2178, 129.2771) radius 1.5
  circle C12 centre (182.6526, 115.6522) radius 1.5
  circle C13 centre (187.4748, 103.1839) radius 1.375
  circle C14 centre (177.252, 111.6581) radius 1.625
  circle C15 centre (140.0835, 100.158) radius 1.5
  circle C16 centre (167.394, 120.4677) radius 1.75
  circle C17 centre (156.0689, 100.8516) radius 1.75
  circle C18 centre (153.8851, 127.7872) radius 1.625
  circle C19 centre (182.6526, 107.6644) radius 1.5
  circle C20 centre (137.3515, 107.6641) radius 1.5
  circle C21 centre (148.6767, 113.655) radius 1.75
  circle C22 centre (134.0992, 99.184) radius 1.375
  circle C23 centre (145.627, 136.5564) radius 1.375
  circle C24 centre (161.7789, 106.1896) radius 1.875
  circle C25 centre (147.0902, 100.2193) radius 1.625
  circle C26 centre (140.0834, 123.158) radius 1.5
  circle C27 centre (153.6046, 83.629) radius 1.375
  circle C28 centre (183.7564, 95.4627) radius 1.375
  circle C29 centre (162.1505, 140.3277) radius 1.375
  circle C30 centre (162.0813, 128.7824) radius 1.625
  circle C31 centre (160.0019, 134.6581) radius 1.5
  arc A14 centre (184.5019, 136.1581) radius 7.5 clockwise from (184.5019, 143.6581) to (192.0019, 136.1581)
  arc A15 centre (135.5019, 136.1581) radius 7.5 clockwise from (128.0019, 136.1581) to (135.5019, 143.6581)
  arc A16 centre (135.5019, 87.1581) radius 7.5 clockwise from (135.5019, 79.6581) to (128.0019, 87.1581)
  arc A17 centre (184.5019, 87.1581) radius 7.5 clockwise from (192.0019, 87.1581) to (184.5019, 79.6581)
  circle C32 centre (143.2533, 115.7863) radius 1.625
  circle C33 centre (174.7862, 94.0392) radius 1.5
  circle C34 centre (177.9274, 134.1358) radius 1.375
  circle C35 centre (131.5731, 115.9431) radius 1.375
  circle C36 centre (147.0902, 123.097) radius 1.625
  circle C37 centre (152.1354, 133.271) radius 1.5
  circle C38 centre (155.3502, 108.2784) radius 1.875
  circle C39 centre (160.0019, 123.1581) radius 1.75
  circle C40 centre (167.8686, 90.0452) radius 1.5
  circle C41 centre (150.0428, 105.908) radius 1.75
  circle C42 centre (131.5731, 107.3732) radius 1.375
  circle C43 centre (160.0022, 88.6581) radius 1.5
  circle C44 centre (137.3514, 115.6519) radius 1.5
  circle C45 centre (188.752, 111.6581) radius 1.375
  circle C46 centre (160.002, 111.6581) radius 2
  circle C47 centre (145.218, 94.039) radius 1.5
  circle C48 centre (134.0992, 124.1323) radius 1.375
  circle C49 centre (145.627, 86.7599) radius 1.375
  circle C50 centre (138.9268, 92.1032) radius 1.375
  circle C51 centre (179.9206, 123.1582) radius 1.5
  circle C52 centre (153.6046, 139.6873) radius 1.375
  circle C53 centre (170.5056, 138.4208) radius 1.375
  circle C54 centre (174.786, 129.2772) radius 1.5
  circle C55 centre (162.1505, 82.9885) radius 1.375
  circle C56 centre (163.9354, 100.8517) radius 1.75
  circle C57 centre (153.8851, 95.5291) radius 1.625
  circle C58 centre (175.2761, 103.6417) radius 1.625
  circle C59 centre (169.9614, 105.9082) radius 1.75
  circle C60 centre (162.0813, 94.5339) radius 1.625
  circle C61 centre (143.2533, 107.5299) radius 1.625
  circle C62 centre (152.1357, 90.0452) radius 1.5
  circle C63 centre (171.3273, 113.6552) radius 1.75
  circle C64 centre (179.9207, 100.1582) radius 1.5
  circle C65 centre (170.5056, 84.8955) radius 1.375
  circle C66 centre (152.6099, 120.4676) radius 1.75
  circle C67 centre (169.8011, 97.4617) radius 1.625
  circle C68 centre (138.9268, 131.2131) radius 1.375
  circle C69 centre (133.642, 238.4361) radius 1.875
  circle C70 centre (141.6585, 228.9119) radius 1.625
  circle C71 centre (139.1106, 242.4092) radius 1.875
  circle C72 centre (149.8375, 220.4317) radius 1.375
  circle C73 centre (137.0218, 248.8379) radius 1.875
  circle C74 centre (111.1643, 226.2607) radius 1.375
  circle C75 centre (147.8385, 234.3869) radius 1.625
  circle C76 centre (142.1162, 216.7133) radius 1.375
  circle C77 centre (151.2609, 258.9703) radius 1.5
  circle C78 centre (137.636, 221.5355) radius 1.5
  circle C79 centre (125.1678, 216.7133) radius 1.375
  circle C80 centre (133.642, 226.9361) radius 1.625
  circle C81 centre (122.1419, 264.1046) radius 1.5
  circle C82 centre (142.4516, 236.7941) radius 1.75
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sketch "Sketch55" plane through (0, 0, 100.89) normal (0, 0, 1) x axis (-1, 0, 0)
  line L1 (-70.4881, 25.0153) -> (-77.9184, 36.8936)
  line L2 (-57.3532, 20.7882) -> (-62.858, 20.7882)
  line L3 (-44.6522, 33.8527) -> (-50.4482, 24.6087)
  line L4 (-0.9873, 49.5999) -> (-39.979, 37.4526)
  line L5 (33.6145, -91.6878) -> (56.037, -74.7812)
  curve K1 (-2.6931, -89.0142) -> (33.6145, -91.6878)
  line L6 (-103.79, -106.0016) -> (-39.0028, -106.0016)
  line L7 (-115.79, 34.151) -> (-115.79, -94.0016)
  line L8 (-84.7008, 40.651) -> (-109.29, 40.651)
  line L9 (-148.79, 118.79) -> (148.79, 118.79)
  line L10 (-163.79, -103.79) -> (-163.79, 103.79)
  line L11 (148.79, -118.79) -> (-148.79, -118.79)
  line L12 (163.79, 103.79) -> (163.79, -103.79)
  circle C1 centre (-12.4884, -95.702) radius 3
  circle C2 centre (132.3797, 40.2075) radius 4
  circle C3 centre (-60, 32) radius 3
  arc A1 centre (-84.7008, 32.651) radius 8 clockwise from (-84.7008, 40.651) to (-77.9184, 36.8936)
  arc A2 centre (-62.858, 29.7882) radius 9 clockwise from (-62.858, 20.7882) to (-70.4881, 25.0153)
  arc A3 centre (-57.3532, 28.9382) radius 8.15 clockwise from (-50.4482, 24.6087) to (-57.3532, 20.7882)
  arc A4 centre (-37.4507, 29.3373) radius 8.5 clockwise from (-44.6522, 33.8527) to (-39.979, 37.4526)
  arc A5 centre (58.7121, 1.7076) radius 76.5356 clockwise from (-0.9873, 49.5999) to (56.037, -74.7812)
  arc A6 centre (-12.4884, -96.8605) radius 12.5504 clockwise from (-12.4884, -96.8605) to (-24.7901, -94.3742)
  arc A7 centre (-39.0028, -91.5016) radius 14.5 clockwise from (-24.7901, -94.3742) to (-39.0028, -106.0016)
  arc A8 centre (-103.79, -94.0016) radius 12 clockwise from (-103.79, -106.0016) to (-115.79, -94.0016)
  arc A9 centre (-109.29, 34.151) radius 6.5 clockwise from (-115.79, 34.151) to (-109.29, 40.651)
  arc A10 centre (148.79, 103.79) radius 15 clockwise from (148.79, 118.79) to (163.79, 103.79)
  arc A11 centre (-148.79, 103.79) radius 15 clockwise from (-163.79, 103.79) to (-148.79, 118.79)
  arc A12 centre (-148.79, -103.79) radius 15 clockwise from (-148.79, -118.79) to (-163.79, -103.79)
  arc A13 centre (148.79, -103.79) radius 15 clockwise from (163.79, -103.79) to (148.79, -118.79)
  arc A14 centre (148.79, -103.79) radius 10 clockwise from (140.1297, -108.79) to (153.79, -95.1297)
  arc A15 centre (0, -108.79) radius 10 clockwise from (-10, -108.79) to (10, -108.79)
  arc A16 centre (-148.79, -103.79) radius 10 clockwise from (-153.79, -95.1297) to (-140.1297, -108.79)
  arc A17 centre (148.79, 103.79) radius 10 clockwise from (153.79, 95.1297) to (140.1297, 108.79)
  arc A18 centre (0, 108.79) radius 10 clockwise from (10, 108.79) to (-10, 108.79)
  arc A19 centre (-148.79, 103.79) radius 10 clockwise from (-140.0971, 108.7329) to (-153.7329, 95.0971)
  circle C4 centre (148.79, -103.79) radius 3
  circle C5 centre (0, -108.79) radius 3
  circle C6 centre (-148.79, -103.79) radius 3
  circle C7 centre (-148.79, 103.79) radius 3
  circle C8 centre (0, 108.79) radius 3
  circle C9 centre (148.79, 103.79) radius 3
  concentric A14 C4
  concentric A15 C5
  concentric A16 C6
  concentric A11 C7
  concentric A18 C8
  concentric A10 C9
  dimension "d371" diameter C4 = 6 (= "top_mount")
  dimension "d372" diameter C5 = 6 (= "top_mount")
  dimension "d373" diameter C6 = 6 (= "top_mount")
  dimension "d374" diameter C7 = 6 (= "top_mount")
  dimension "d375" diameter C8 = 6 (= "top_mount")
  dimension "d376" diameter C9 = 6 (= "top_mount")
extrude "Extrude2" cut sketch "Sketch55" profile of C4 C5 C6 C7 C8 C9 against normal blind 2
sketch "Sketch56" plane through (0, -130, 0) normal (0, -1, 0) x axis (1, 0, 0)
  line L1 (128.79, 72.18) -> (128.79, 23.18)
  line L2 (72.29, 79.68) -> (121.29, 79.68)
  line L3 (64.79, 23.18) -> (64.79, 72.18)
  line L4 (121.29, 15.68) -> (72.29, 15.68)
  line L5 (128.79, 79.68) -> (64.79, 79.68)
  line L6 (128.79, 15.68) -> (128.79, 79.68)
  line L7 (64.79, 15.68) -> (128.79, 15.68)
  line L8 (64.79, 79.68) -> (64.79, 15.68)
  line L9 (123.79, 23.18) -> (123.79, 72.18)
  line L10 (72.29, 20.68) -> (121.29, 20.68)
  line L11 (69.79, 72.18) -> (69.79, 23.18)
  line L12 (121.29, 74.68) -> (72.29, 74.68)
  line L13 (64.79, 23.18) -> (64.79, 72.18)
  line L14 (121.29, 15.68) -> (72.29, 15.68)
  line L15 (128.79, 72.18) -> (128.79, 23.18)
  line L16 (72.29, 79.68) -> (121.29, 79.68)
  line L17 (70.5222, 21.4122) -> (66.9867, 17.8767)
  circle C1 centre (108.2289, 60.5917) radius 1.625
  circle C2 centre (119.79, 47.68) radius 1.5
  circle C3 centre (92.505, 76.1088) radius 1.375
  circle C4 centre (98.7871, 36.3546) radius 1.75
  circle C5 centre (119.2677, 29.7545) radius 1.375
  circle C6 centre (114.4091, 32.8959) radius 1.5
  circle C7 centre (96.79, 18.9299) radius 1.375
  circle C8 centre (71.8918, 62.0549) radius 1.375
  circle C9 centre (73.79, 47.6797) radius 1.5
  circle C10 centre (113.9142, 45.6006) radius 1.625
  circle C11 centre (79.1711, 32.8957) radius 1.5
  circle C12 centre (80.661, 53.7968) radius 1.625
  circle C13 centre (100.9182, 64.4286) radius 1.625
  circle C14 centre (101.075, 76.1088) radius 1.375
  circle C15 centre (112.919, 53.7968) radius 1.625
  circle C16 centre (100.784, 25.0293) radius 1.5
  circle C17 centre (123.5526, 37.1763) radius 1.375
  circle C18 centre (96.79, 30.4299) radius 1.625
  circle C19 centre (110.9865, 37.8808) radius 1.625
  circle C20 centre (100.1698, 52.3317) radius 1.875
  circle C21 centre (85.9835, 51.613) radius 1.75
  circle C22 centre (79.1709, 62.4639) radius 1.5
  circle C23 centre (121.6882, 62.0549) radius 1.375
  circle C24 centre (91.0401, 37.7205) radius 1.75
  circle C25 centre (96.79, 47.6799) radius 2
  circle C26 centre (74.3123, 29.7545) radius 1.375
  circle C27 centre (79.6658, 45.6006) radius 1.625
  circle C28 centre (92.7962, 25.0293) radius 1.5
  circle C29 centre (116.345, 68.7551) radius 1.375
  arc A1 centre (121.29, 23.18) radius 7.5 clockwise from (128.79, 23.18) to (121.29, 15.68)
  arc A2 centre (121.29, 72.18) radius 7.5 clockwise from (121.29, 79.68) to (128.79, 72.18)
  arc A3 centre (72.29, 72.18) radius 7.5 clockwise from (64.79, 72.18) to (72.29, 79.68)
  arc A4 centre (72.29, 23.18) radius 7.5 clockwise from (72.29, 15.68) to (64.79, 23.18)
  circle C30 centre (85.2901, 27.7612) radius 1.5
  circle C31 centre (112.9855, 23.9255) radius 1.375
  circle C32 centre (70.0274, 37.1763) radius 1.375
  circle C33 centre (102.2586, 45.903) radius 1.875
  circle C34 centre (105.5994, 55.072) radius 1.75
  circle C35 centre (104.8065, 32.4058) radius 1.625
  circle C36 centre (82.5935, 37.8808) radius 1.625
  circle C37 centre (96.79, 41.9299) radius 1.875
  circle C38 centre (93.4102, 52.3317) radius 1.875
  circle C39 centre (125.4596, 45.5314) radius 1.375
  circle C40 centre (75.177, 55.5462) radius 1.5
  circle C41 centre (92.796, 70.3304) radius 1.5
  circle C42 centre (77.235, 68.7551) radius 1.375
  circle C43 centre (91.3214, 45.903) radius 1.875
  circle C44 centre (88.7735, 32.4058) radius 1.625
  circle C45 centre (100.7838, 70.3305) radius 1.5
  circle C46 centre (85.9836, 43.7465) radius 1.75
  circle C47 centre (68.1204, 45.5314) radius 1.375
  circle C48 centre (108.2899, 67.5985) radius 1.5
  circle C49 centre (105.5996, 40.2879) radius 1.75
  circle C50 centre (114.4089, 62.4641) radius 1.5
  circle C51 centre (85.2899, 67.5984) radius 1.5
  circle C52 centre (85.3511, 60.5917) radius 1.625
  circle C53 centre (118.4029, 55.5465) radius 1.5
  circle C54 centre (80.5945, 23.9255) radius 1.375
  circle C55 centre (109.2642, 73.5827) radius 1.375
  circle C56 centre (108.29, 47.68) radius 1.75
  circle C57 centre (108.2901, 27.7613) radius 1.5
  circle C58 centre (105.2642, 20.2071) radius 1.375
  circle C59 centre (68.7608, 54.0773) radius 1.375
  circle C60 centre (75.1771, 39.8133) radius 1.5
  circle C61 centre (124.8192, 54.0773) radius 1.375
  circle C62 centre (91.0399, 57.6391) radius 1.75
  circle C63 centre (88.3158, 20.2071) radius 1.375
  circle C64 centre (98.7868, 59.0052) radius 1.75
  circle C65 centre (84.3158, 73.5827) radius 1.375
  circle C66 centre (92.6618, 64.4286) radius 1.625
  arc A5 centre (121.29, 72.18) radius 2.5 clockwise from (121.29, 74.68) to (123.79, 72.18)
  arc A6 centre (121.29, 23.18) radius 2.5 clockwise from (123.79, 23.18) to (121.29, 20.68)
  arc A7 centre (72.29, 23.18) radius 2.5 clockwise from (72.29, 20.68) to (69.79, 23.18)
  arc A8 centre (72.29, 72.18) radius 2.5 clockwise from (69.79, 72.18) to (72.29, 74.68)
  arc A9 centre (72.29, 72.18) radius 7.5 clockwise from (64.79, 72.18) to (72.29, 79.68)
  arc A10 centre (72.29, 23.18) radius 7.5 clockwise from (72.29, 15.68) to (64.79, 23.18)
  arc A11 centre (121.29, 23.18) radius 7.5 clockwise from (128.79, 23.18) to (121.29, 15.68)
  arc A12 centre (121.29, 72.18) radius 7.5 clockwise from (121.29, 79.68) to (128.79, 72.18)
  circle C67 centre (118.403, 39.8135) radius 1.5
  point P104 (66.9867, 17.8767)
  point P105 (70.5222, 21.4122)
  horizontal L5
  vertical L6
  horizontal L7
  vertical L8
  collinear L2 L5
  collinear L3 L8
  collinear L4 L7
  collinear L1 L6
  midpoint A4 P104
  midpoint A7 P105
copy_paste "CopyPaste2"
step "Arrange10" AngleFromX 0 Priority 500 AngleFromX 0 Priority 500 AngleFromX 0 Priority 500 originOffsetX 0 originOffsetY 0 envelopeLength 270 envelopeWidth 400 envelopeSpacing 0 grainDirection 0 objectSpacing 20 frameWidth 10 placementClearance 0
